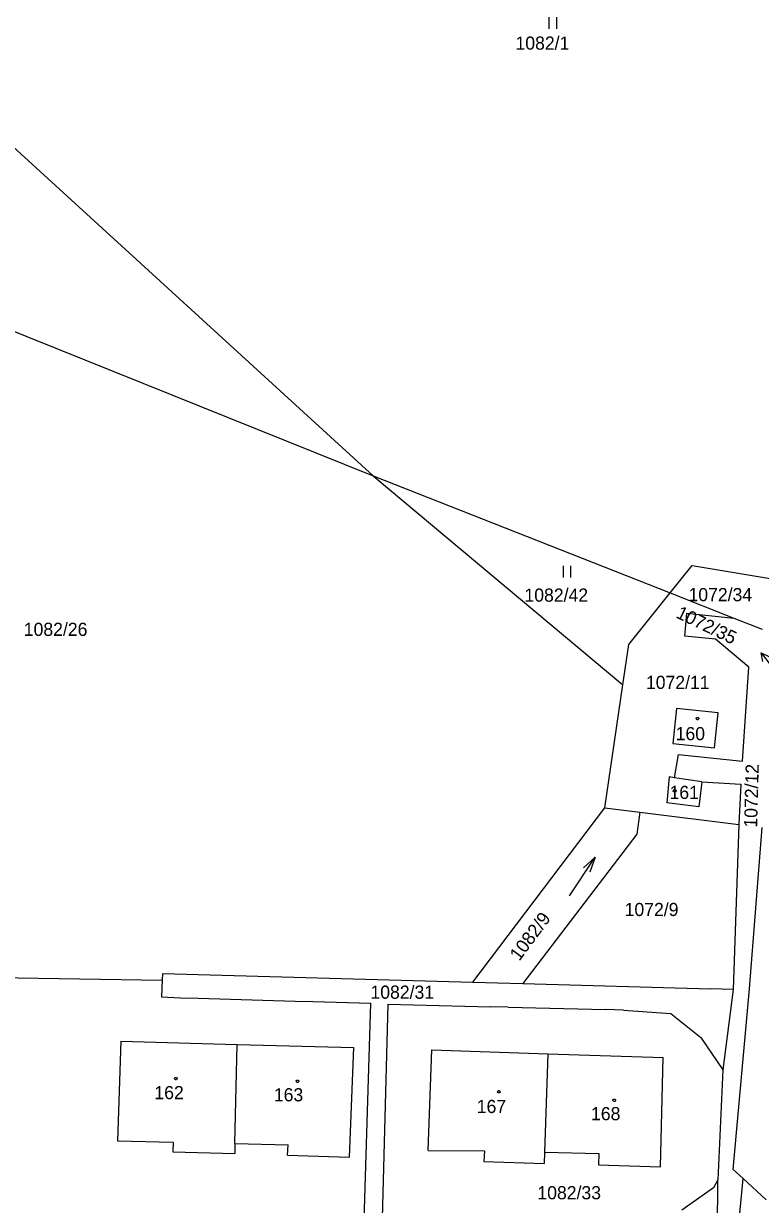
# Model space of a CAD drawing. Extents: x -852001 to -842497, y -1063614 to -1052182.
# Drawn here: x -849610.9 to -849515.7, y -1056247.4 to -1056094.9 of the extents above; entities that cross this region are included whole.
import ezdxf

# ---------------------------------------------------------------- set-up
doc = ezdxf.new("R2010")
doc.units = 0
for name, color, linetype in [('Default', 7, 'Continuous'), ('KN_HRANICE', 7, 'Continuous'), ('KN_KULTURY', 7, 'Continuous'), ('KN_PARCELY', 7, 'Continuous')]:
    doc.layers.add(name, color=color, linetype=linetype)

# ---------------------------------------------------------------- blocks, each defined once
blk = doc.blocks.new('306')
at = {"layer": 'Default'}
for p, q in [((-0.5, 1.5), (-0.5, 0)), ((0.5, 0), (0.5, 1.5))]:
    blk.add_line(p, q, dxfattribs=at)
blk = doc.blocks.new('802')
at = {"layer": 'Default'}
blk.add_line((-3, 0), (3, 0), dxfattribs=at)
blk.add_lwpolyline([(1, 0.5), (3, 0), (1, -0.5)], dxfattribs=at)
blk = doc.blocks.new('10292')
at = {"layer": 'Default'}
blk.add_line((0, 3), (0, 0), dxfattribs=at)
blk.add_lwpolyline([(-0.5, 2), (0, 3), (0.5, 2)], dxfattribs=at)
blk = doc.blocks.new('402')
at = {"layer": 'Default'}
blk.add_lwpolyline([(0.09, 0.15), (0.18, 0), (0.09, -0.15), (-0.09, -0.15), (-0.18, 0), (-0.09, 0.15), (0.09, 0.15)], dxfattribs=at)

msp = doc.modelspace()

# ---------------------------------------------------------------- linework, layer by layer
at = {"layer": 'KN_HRANICE'}
for p, q in [((-849629.86, -1056094.78), (-849565.73, -1056153.32)), ((-849629.86, -1056094.78), (-849565.73, -1056153.32)), ((-849614.89, -1056133.59), (-849565.73, -1056153.32)), ((-849614.89, -1056133.59), (-849565.73, -1056153.32)), ((-849565.73, -1056153.32), (-849533.49, -1056180.31)), ((-849565.73, -1056153.32), (-849527.38, -1056168.45)), ((-849565.73, -1056153.32), (-849533.49, -1056180.31)), ((-849565.73, -1056153.32), (-849527.38, -1056168.45)), ((-849527.38, -1056168.45), (-849524.53, -1056164.91)), ((-849527.38, -1056168.45), (-849524.53, -1056164.91)), ((-849524.53, -1056164.91), (-849514.22, -1056166.62)), ((-849524.53, -1056164.91), (-849514.22, -1056166.62)), ((-849532.73, -1056175.12), (-849527.38, -1056168.45)), ((-849532.73, -1056175.12), (-849527.38, -1056168.45)), ((-849527.38, -1056168.45), (-849519.17, -1056171.69)), ((-849527.38, -1056168.45), (-849519.17, -1056171.69)), ((-849525.47, -1056174.02), (-849525.23, -1056171.06)), ((-849525.47, -1056174.02), (-849525.23, -1056171.06)), ((-849525.23, -1056171.06), (-849519.17, -1056171.69)), ((-849525.23, -1056171.06), (-849519.17, -1056171.69)), ((-849519.17, -1056171.69), (-849515.51, -1056173.13)), ((-849519.17, -1056171.69), (-849515.51, -1056173.13)), ((-849533.49, -1056180.31), (-849532.73, -1056175.12)), ((-849533.49, -1056180.31), (-849532.73, -1056175.12)), ((-849521.53, -1056174.4), (-849525.47, -1056174.02)), ((-849521.53, -1056174.4), (-849525.47, -1056174.02)), ((-849517.22, -1056178.04), (-849521.53, -1056174.4)), ((-849517.22, -1056178.04), (-849521.53, -1056174.4)), ((-849518.02, -1056190.16), (-849517.22, -1056178.04)), ((-849518.02, -1056190.16), (-849517.22, -1056178.04)), ((-849535.83, -1056196.19), (-849533.49, -1056180.31)), ((-849535.83, -1056196.19), (-849533.49, -1056180.31)), ((-849526.56, -1056183.37), (-849527.04, -1056187.89)), ((-849526.56, -1056183.37), (-849527.04, -1056187.89)), ((-849521.2, -1056183.94), (-849526.56, -1056183.37)), ((-849521.2, -1056183.94), (-849526.56, -1056183.37)), ((-849521.67, -1056188.46), (-849521.2, -1056183.94)), ((-849521.67, -1056188.46), (-849521.2, -1056183.94)), ((-849527.04, -1056187.89), (-849521.67, -1056188.46)), ((-849527.04, -1056187.89), (-849521.67, -1056188.46)), ((-849526.8, -1056192.31), (-849526.31, -1056189.3)), ((-849526.8, -1056192.31), (-849526.31, -1056189.3)), ((-849526.31, -1056189.3), (-849518.02, -1056190.16)), ((-849526.31, -1056189.3), (-849518.02, -1056190.16)), ((-849527.49, -1056192.21), (-849527.83, -1056195.55)), ((-849527.49, -1056192.21), (-849527.83, -1056195.55)), ((-849526.8, -1056192.31), (-849527.49, -1056192.21)), ((-849526.8, -1056192.31), (-849527.49, -1056192.21)), ((-849523.27, -1056192.83), (-849526.8, -1056192.31)), ((-849523.27, -1056192.83), (-849526.8, -1056192.31)), ((-849523.27, -1056192.83), (-849523.66, -1056196.06)), ((-849523.27, -1056192.83), (-849523.66, -1056196.06)), ((-849523.27, -1056192.83), (-849518.25, -1056193.14)), ((-849523.27, -1056192.83), (-849518.25, -1056193.14)), ((-849518.25, -1056193.14), (-849518.5, -1056198.37)), ((-849518.25, -1056193.14), (-849518.5, -1056198.37)), ((-849552.87, -1056218.73), (-849535.83, -1056196.19)), ((-849552.87, -1056218.73), (-849535.83, -1056196.19)), ((-849535.83, -1056196.19), (-849531.3, -1056196.76)), ((-849535.83, -1056196.19), (-849531.3, -1056196.76)), ((-849523.66, -1056196.06), (-849527.83, -1056195.55)), ((-849523.66, -1056196.06), (-849527.83, -1056195.55)), ((-849531.3, -1056196.76), (-849531.68, -1056199.6)), ((-849531.3, -1056196.76), (-849531.68, -1056199.6)), ((-849531.3, -1056196.76), (-849518.5, -1056198.37)), ((-849531.3, -1056196.76), (-849518.5, -1056198.37)), ((-849531.68, -1056199.6), (-849546.39, -1056218.91)), ((-849531.68, -1056199.6), (-849546.39, -1056218.91)), ((-849518.5, -1056198.37), (-849519.23, -1056219.66)), ((-849518.5, -1056198.37), (-849519.23, -1056219.66)), ((-849517.12, -1056219.58), (-849515.49, -1056198.73)), ((-849517.12, -1056219.58), (-849515.49, -1056198.73)), ((-849633.22, -1056217.81), (-849593, -1056218.48)), ((-849633.22, -1056217.81), (-849593, -1056218.48)), ((-849592.97, -1056217.6), (-849593, -1056218.48)), ((-849592.97, -1056217.6), (-849593, -1056218.48)), ((-849592.97, -1056217.6), (-849552.87, -1056218.73)), ((-849592.97, -1056217.6), (-849552.87, -1056218.73)), ((-849593, -1056218.48), (-849593.09, -1056220.61)), ((-849593, -1056218.48), (-849593.09, -1056220.61)), ((-849552.87, -1056218.73), (-849546.39, -1056218.91)), ((-849552.87, -1056218.73), (-849546.39, -1056218.91)), ((-849546.39, -1056218.91), (-849522.19, -1056219.6)), ((-849546.39, -1056218.91), (-849522.19, -1056219.6)), ((-849593.09, -1056220.61), (-849590.62, -1056220.75)), ((-849593.09, -1056220.61), (-849590.62, -1056220.75)), ((-849590.62, -1056220.75), (-849588.34, -1056220.78)), ((-849590.62, -1056220.75), (-849588.34, -1056220.78)), ((-849588.34, -1056220.78), (-849575.82, -1056221.16)), ((-849588.34, -1056220.78), (-849575.82, -1056221.16)), ((-849519.23, -1056219.66), (-849522.19, -1056219.6)), ((-849519.23, -1056219.66), (-849522.19, -1056219.6)), ((-849519.23, -1056219.66), (-849520.58, -1056230.06)), ((-849519.23, -1056219.66), (-849520.58, -1056230.06)), ((-849519.24, -1056242.93), (-849517.12, -1056219.58)), ((-849519.24, -1056242.93), (-849517.12, -1056219.58)), ((-849575.82, -1056221.16), (-849573.55, -1056221.23)), ((-849575.82, -1056221.16), (-849573.55, -1056221.23)), ((-849573.55, -1056221.23), (-849566.03, -1056221.45)), ((-849573.55, -1056221.23), (-849566.03, -1056221.45)), ((-849567, -1056252.9), (-849566.03, -1056221.45)), ((-849567, -1056252.9), (-849566.03, -1056221.45)), ((-849563.83, -1056221.55), (-849564.68, -1056252.6)), ((-849563.83, -1056221.55), (-849564.68, -1056252.6)), ((-849563.83, -1056221.55), (-849550.57, -1056221.9)), ((-849563.83, -1056221.55), (-849550.57, -1056221.9)), ((-849548.32, -1056221.93), (-849550.57, -1056221.9)), ((-849548.32, -1056221.93), (-849550.57, -1056221.9)), ((-849548.32, -1056221.93), (-849535.73, -1056222.24)), ((-849548.32, -1056221.93), (-849535.73, -1056222.24)), ((-849533.4, -1056222.32), (-849535.73, -1056222.24)), ((-849533.4, -1056222.32), (-849535.73, -1056222.24)), ((-849533.4, -1056222.32), (-849527.28, -1056222.76)), ((-849533.4, -1056222.32), (-849527.28, -1056222.76)), ((-849527.28, -1056222.76), (-849523.4, -1056225.85)), ((-849527.28, -1056222.76), (-849523.4, -1056225.85)), ((-849598.32, -1056226.32), (-849598.78, -1056239.21)), ((-849598.32, -1056226.32), (-849598.78, -1056239.21)), ((-849598.32, -1056226.32), (-849583.29, -1056226.79)), ((-849598.32, -1056226.32), (-849583.29, -1056226.79)), ((-849583.59, -1056239.57), (-849583.29, -1056226.79)), ((-849583.59, -1056239.57), (-849583.29, -1056226.79)), ((-849583.29, -1056226.79), (-849568.24, -1056227.17)), ((-849583.29, -1056226.79), (-849568.24, -1056227.17)), ((-849523.4, -1056225.85), (-849520.58, -1056230.06)), ((-849523.4, -1056225.85), (-849520.58, -1056230.06)), ((-849568.82, -1056241.34), (-849568.24, -1056227.17)), ((-849568.82, -1056241.34), (-849568.24, -1056227.17)), ((-849558.62, -1056240.45), (-849558.17, -1056227.46)), ((-849558.62, -1056240.45), (-849558.17, -1056227.46)), ((-849558.17, -1056227.46), (-849543.2, -1056227.96)), ((-849558.17, -1056227.46), (-849543.2, -1056227.96)), ((-849543.2, -1056227.96), (-849543.62, -1056240.68)), ((-849543.2, -1056227.96), (-849543.62, -1056240.68)), ((-849543.2, -1056227.96), (-849528.27, -1056228.45)), ((-849543.2, -1056227.96), (-849528.27, -1056228.45)), ((-849528.65, -1056242.55), (-849528.27, -1056228.45)), ((-849528.65, -1056242.55), (-849528.27, -1056228.45)), ((-849520.58, -1056230.06), (-849521.22, -1056244.23)), ((-849520.58, -1056230.06), (-849521.22, -1056244.23)), ((-849598.78, -1056239.21), (-849591.59, -1056239.38)), ((-849598.78, -1056239.21), (-849591.59, -1056239.38)), ((-849591.59, -1056239.38), (-849591.62, -1056240.61)), ((-849591.59, -1056239.38), (-849591.62, -1056240.61)), ((-849591.62, -1056240.61), (-849583.62, -1056240.86)), ((-849591.62, -1056240.61), (-849583.62, -1056240.86)), ((-849583.59, -1056239.57), (-849583.62, -1056240.86)), ((-849583.59, -1056239.57), (-849583.62, -1056240.86)), ((-849583.59, -1056239.57), (-849576.72, -1056239.73)), ((-849583.59, -1056239.57), (-849576.72, -1056239.73)), ((-849576.82, -1056241.08), (-849576.72, -1056239.73)), ((-849576.82, -1056241.08), (-849576.72, -1056239.73)), ((-849558.62, -1056240.45), (-849551.38, -1056240.51)), ((-849558.62, -1056240.45), (-849551.38, -1056240.51)), ((-849551.38, -1056240.51), (-849551.46, -1056241.87)), ((-849551.38, -1056240.51), (-849551.46, -1056241.87)), ((-849543.62, -1056240.68), (-849543.67, -1056242.12)), ((-849543.62, -1056240.68), (-849543.67, -1056242.12)), ((-849543.62, -1056240.68), (-849536.61, -1056240.84)), ((-849543.62, -1056240.68), (-849536.61, -1056240.84)), ((-849536.61, -1056240.84), (-849536.64, -1056242.31)), ((-849536.61, -1056240.84), (-849536.64, -1056242.31)), ((-849576.82, -1056241.08), (-849568.82, -1056241.34)), ((-849576.82, -1056241.08), (-849568.82, -1056241.34)), ((-849551.46, -1056241.87), (-849543.67, -1056242.12)), ((-849551.46, -1056241.87), (-849543.67, -1056242.12)), ((-849536.64, -1056242.31), (-849528.65, -1056242.55)), ((-849536.64, -1056242.31), (-849528.65, -1056242.55)), ((-849517.97, -1056244.08), (-849519.24, -1056242.93)), ((-849517.97, -1056244.08), (-849519.24, -1056242.93)), ((-849521.78, -1056245.26), (-849525.87, -1056248.18)), ((-849521.78, -1056245.26), (-849525.87, -1056248.18)), ((-849521.22, -1056244.23), (-849521.78, -1056245.26)), ((-849521.22, -1056244.23), (-849521.78, -1056245.26)), ((-849521.28, -1056252.42), (-849521.22, -1056244.23)), ((-849521.28, -1056252.42), (-849521.22, -1056244.23)), ((-849518.79, -1056252.77), (-849517.97, -1056244.08)), ((-849518.79, -1056252.77), (-849517.97, -1056244.08)), ((-849514.98, -1056246.81), (-849517.97, -1056244.08)), ((-849514.98, -1056246.81), (-849517.97, -1056244.08))]:
    msp.add_line(p, q, dxfattribs=at)

# ---------------------------------------------------------------- block references
at = {"layer": 'KN_KULTURY'}
for name, p in [('306', (-849542.54, -1056095.59)), ('306', (-849542.54, -1056095.59)), ('306', (-849540.7, -1056166.46)), ('306', (-849540.7, -1056166.46)), ('402', (-849523.86, -1056184.67)), ('402', (-849523.86, -1056184.67)), ('402', (-849526.8, -1056194)), ('402', (-849526.8, -1056194)), ('402', (-849591.23, -1056231.17)), ('402', (-849591.23, -1056231.17)), ('402', (-849575.51, -1056231.51)), ('402', (-849575.51, -1056231.51)), ('402', (-849549.51, -1056232.88)), ('402', (-849549.51, -1056232.88)), ('402', (-849534.6, -1056233.97)), ('402', (-849534.6, -1056233.97))]:
    msp.add_blockref(name, p, dxfattribs=at)
at = {"layer": 'KN_KULTURY', "rotation": 56.60823000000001}
msp.add_blockref('802', (-849538.72, -1056205.07), dxfattribs=at)
msp.add_blockref('802', (-849538.72, -1056205.07), dxfattribs=at)
at = {"layer": 'KN_PARCELY', "rotation": 37.987102}
msp.add_blockref('10292', (-849513.8, -1056178.56), dxfattribs=at)
msp.add_blockref('10292', (-849513.8, -1056178.56), dxfattribs=at)

# ---------------------------------------------------------------- texts
at = {"layer": 'KN_PARCELY'}
for s, p in [('1082/1', (-849547.36, -1056098.29)), ('1082/1', (-849547.36, -1056098.29)), ('1082/42', (-849546.2, -1056169.58)), ('1082/42', (-849546.2, -1056169.58)), ('1072/34', (-849525.01, -1056169.52)), ('1072/34', (-849525.01, -1056169.52)), ('1082/26', (-849610.87, -1056174)), ('1082/26', (-849610.87, -1056174)), ('1072/11', (-849530.51, -1056180.85)), ('1072/11', (-849530.51, -1056180.85)), ('160', (-849526.67, -1056187.47)), ('160', (-849526.67, -1056187.47)), ('161', (-849527.46, -1056195.06)), ('161', (-849527.46, -1056195.06)), ('1072/9', (-849533.26, -1056210.18)), ('1072/9', (-849533.26, -1056210.18)), ('1082/31', (-849566.09, -1056220.86)), ('1082/31', (-849566.09, -1056220.86)), ('162', (-849594, -1056233.83)), ('162', (-849594, -1056233.83)), ('163', (-849578.57, -1056234.11)), ('163', (-849578.57, -1056234.11)), ('167', (-849552.36, -1056235.62)), ('167', (-849552.36, -1056235.62)), ('168', (-849537.6, -1056236.55)), ('168', (-849537.6, -1056236.55)), ('1082/33', (-849544.53, -1056246.76)), ('1082/33', (-849544.53, -1056246.76))]:
    msp.add_text(s, height=1.7, dxfattribs=at).set_placement(p)
for s, rotation, p in [('1072/35', 334.378, (-849526.74, -1056171.59)), ('1072/35', 334.378, (-849526.74, -1056171.59)), ('1072/12', 88.407, (-849516.15, -1056198.78)), ('1072/12', 88.407, (-849516.15, -1056198.78)), ('1082/9', 53.342, (-849546.87, -1056216.08)), ('1082/9', 53.342, (-849546.87, -1056216.08))]:
    msp.add_text(s, height=1.7, rotation=rotation, dxfattribs=at).set_placement(p)

doc.saveas('drawing.dxf')
